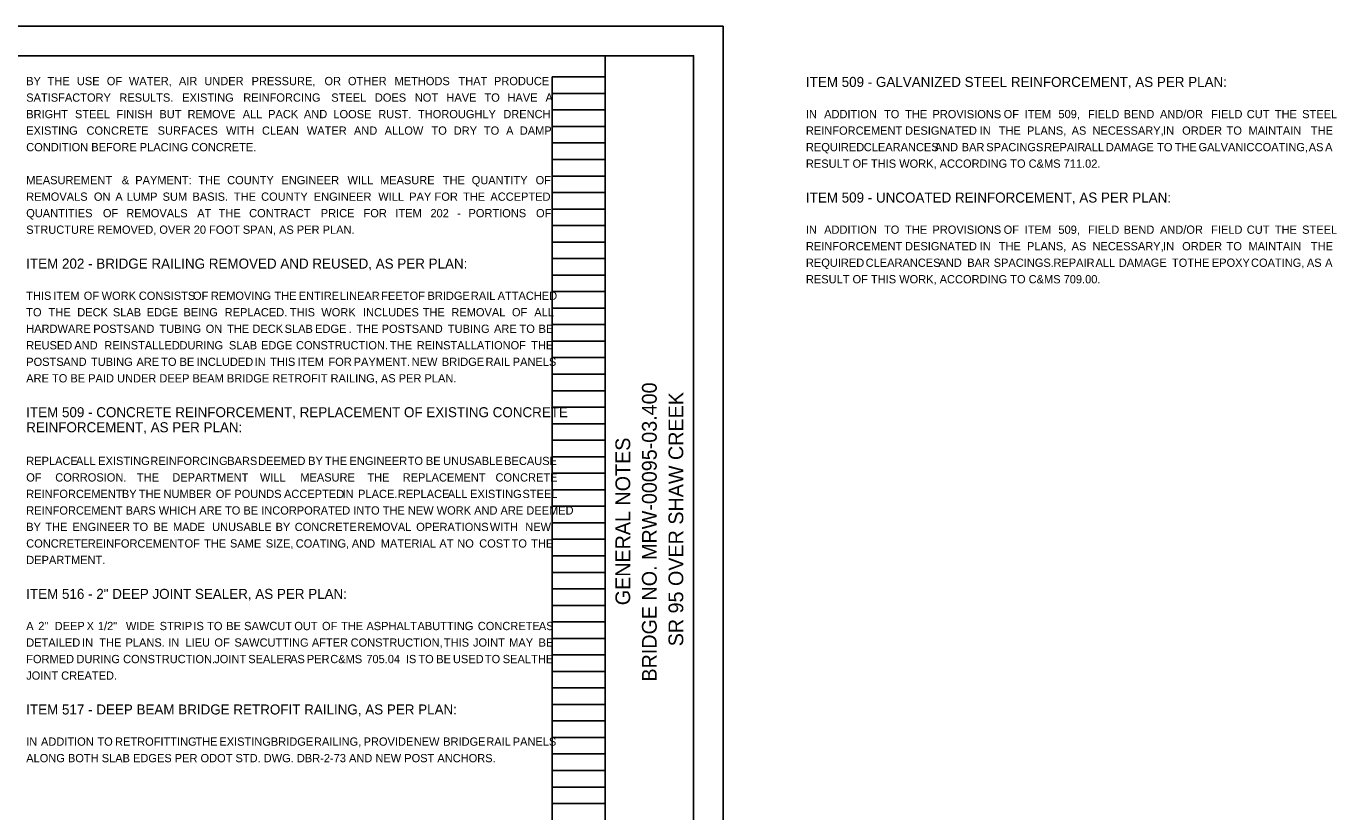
# Model space of a CAD drawing. Extents: x 0 to 44.4, y -4.7 to 22.
# Drawn here: x 22.19 to 44.4, y 8.68 to 22 of the extents above; entities that cross this region are included whole.
import ezdxf

# ---------------------------------------------------------------- set-up
doc = ezdxf.new("R2010")
doc.units = 0
for name, color, linetype in [('SC_Scratch1', 7, 'Continuous'), ('SH_Border', 7, 'Continuous'), ('SH_Cut_Line', 7, 'Continuous'), ('SH_Data', 7, 'Continuous'), ('SH_Text', 7, 'Continuous')]:
    doc.layers.add(name, color=color, linetype=linetype)

msp = doc.modelspace()

# ---------------------------------------------------------------- linework, layer by layer
at = {"layer": 'SC_Scratch1'}
for p, q in [((31.1, 0.98), (31.1, 21.14)), ((31.1, 21.14), (32, 21.14)), ((32, 0.98), (32, 21.14)), ((31.1, 20.86), (32, 20.86)), ((31.1, 20.58), (32, 20.58)), ((31.1, 20.3), (32, 20.3)), ((31.1, 20.02), (32, 20.02)), ((31.1, 19.74), (32, 19.74)), ((31.1, 19.46), (32, 19.46)), ((31.1, 19.18), (32, 19.18)), ((31.1, 18.9), (32, 18.9)), ((31.1, 18.62), (32, 18.62)), ((31.1, 18.34), (32, 18.34)), ((31.1, 18.06), (32, 18.06)), ((31.1, 17.78), (32, 17.78)), ((31.1, 17.5), (32, 17.5)), ((31.1, 17.22), (32, 17.22)), ((31.1, 16.94), (32, 16.94)), ((31.1, 16.66), (32, 16.66)), ((31.1, 16.38), (32, 16.38)), ((31.1, 16.1), (32, 16.1)), ((31.1, 15.82), (32, 15.82)), ((31.1, 15.54), (32, 15.54)), ((31.1, 15.26), (32, 15.26)), ((31.1, 14.98), (32, 14.98)), ((31.1, 14.7), (32, 14.7)), ((31.1, 14.42), (32, 14.42)), ((31.1, 14.14), (32, 14.14)), ((31.1, 13.86), (32, 13.86)), ((31.1, 13.58), (32, 13.58)), ((31.1, 13.3), (32, 13.3)), ((31.1, 13.02), (32, 13.02)), ((31.1, 12.74), (32, 12.74)), ((31.1, 12.46), (32, 12.46)), ((31.1, 12.18), (32, 12.18)), ((31.1, 11.9), (32, 11.9)), ((31.1, 11.62), (32, 11.62)), ((31.1, 11.34), (32, 11.34)), ((31.1, 11.06), (32, 11.06)), ((31.1, 10.78), (32, 10.78)), ((31.1, 10.5), (32, 10.5)), ((31.1, 10.22), (32, 10.22)), ((31.1, 9.94), (32, 9.94)), ((31.1, 9.66), (32, 9.66)), ((31.1, 9.38), (32, 9.38)), ((31.1, 9.1), (32, 9.1)), ((31.1, 8.82), (32, 8.82))]:
    msp.add_line(p, q, dxfattribs=at)
msp.add_lwpolyline([(0, 22), (34, 22), (34, 0), (0, 0)], close=True, dxfattribs=at)
at = {"layer": 'SH_Border'}
msp.add_line((32, 0.5), (32, 21.5), dxfattribs=at)
msp.add_lwpolyline([(1.5, 21.5), (33.5, 21.5), (33.5, 0.5), (1.5, 0.5)], close=True, dxfattribs=at)
at = {"layer": 'SH_Cut_Line'}
msp.add_lwpolyline([(0, 0), (34, 0), (34, 22), (0, 22)], close=True, dxfattribs=at)

# ---------------------------------------------------------------- texts
at = {"layer": 'SH_Data'}
for s, p in [('BRIDGE NO. MRW-00095-03.400', (32.875, 10.888)), ('SR 95 OVER SHAW CREEK', (33.325, 11.486)), ('GENERAL NOTES', (32.425, 12.182))]:
    msp.add_text(s, height=0.25, rotation=90, dxfattribs=at).set_placement(p)
at = {"layer": 'SH_Text'}
for s, height, p in [('BY ', 0.14, (22.187, 21)), ('THE ', 0.14, (22.549, 21)), ('USE ', 0.14, (23.046, 21)), ('OF ', 0.14, (23.553, 21)), ('WATER, ', 0.14, (23.927, 21)), ('AIR ', 0.14, (24.775, 21)), ('UNDER ', 0.14, (25.206, 21)), ('PRESSURE, ', 0.14, (26.007, 21)), ('OR ', 0.14, (27.243, 21)), ('OTHER ', 0.14, (27.641, 21)), ('METHODS ', 0.14, (28.431, 21)), ('THAT ', 0.14, (29.515, 21)), ('PRODUCE ', 0.14, (30.116, 21)), ('ITEM 509 - GALVANIZED STEEL REINFORCEMENT, AS PER PLAN:', 0.17, (35.404, 20.97)), ('SATISFACTORY ', 0.14, (22.187, 20.72)), ('RESULTS. ', 0.14, (23.766, 20.72)), ('EXISTING ', 0.14, (24.831, 20.72)), ('REINFORCING ', 0.14, (25.866, 20.72)), ('STEEL ', 0.14, (27.358, 20.72)), ('DOES ', 0.14, (28.097, 20.72)), ('NOT ', 0.14, (28.774, 20.72)), ('HAVE ', 0.14, (29.31, 20.72)), ('TO ', 0.14, (29.955, 20.72)), ('HAVE ', 0.14, (30.345, 20.72)), ('A', 0.14, (30.99, 20.72)), ('BRIGHT ', 0.14, (22.187, 20.44)), ('STEEL ', 0.14, (23.013, 20.44)), ('FINISH ', 0.14, (23.716, 20.44)), ('BUT ', 0.14, (24.444, 20.44)), ('REMOVE ', 0.14, (24.922, 20.44)), ('ALL ', 0.14, (25.857, 20.44)), ('PACK ', 0.14, (26.288, 20.44)), ('AND ', 0.14, (26.894, 20.44)), ('LOOSE ', 0.14, (27.394, 20.44)), ('RUST. ', 0.14, (28.155, 20.44)), ('THOROUGHLY ', 0.14, (28.828, 20.44)), ('DRENCH ', 0.14, (30.274, 20.44)), ('IN ', 0.14, (35.404, 20.44)), ('ADDITION ', 0.14, (35.713, 20.44)), ('TO ', 0.14, (36.728, 20.44)), ('THE ', 0.14, (37.086, 20.44)), ('PROVISIONS ', 0.14, (37.549, 20.44)), ('OF ', 0.14, (38.756, 20.44)), ('ITEM ', 0.14, (39.113, 20.44)), ('509, ', 0.14, (39.684, 20.44)), ('FIELD ', 0.14, (40.185, 20.44)), ('BEND ', 0.14, (40.79, 20.44)), ('AND/OR ', 0.14, (41.406, 20.44)), ('FIELD ', 0.14, (42.273, 20.44)), ('CUT ', 0.14, (42.877, 20.44)), ('THE ', 0.14, (43.353, 20.44)), ('STEEL ', 0.14, (43.816, 20.44)), ('EXISTING ', 0.14, (22.187, 20.16)), ('CONCRETE ', 0.14, (23.209, 20.16)), ('SURFACES ', 0.14, (24.415, 20.16)), ('WITH ', 0.14, (25.575, 20.16)), ('CLEAN ', 0.14, (26.183, 20.16)), ('WATER ', 0.14, (26.944, 20.16)), ('AND ', 0.14, (27.742, 20.16)), ('ALLOW ', 0.14, (28.263, 20.16)), ('TO ', 0.14, (29.057, 20.16)), ('DRY ', 0.14, (29.434, 20.16)), ('TO ', 0.14, (29.945, 20.16)), ('A ', 0.14, (30.322, 20.16)), ('DAMP ', 0.14, (30.554, 20.16)), ('REINFORCEMENT ', 0.14, (35.404, 20.16)), ('DESIGNATED ', 0.14, (37.085, 20.16)), ('IN ', 0.14, (38.349, 20.16)), ('THE ', 0.14, (38.673, 20.16)), ('PLANS, ', 0.14, (39.151, 20.16)), ('AS ', 0.14, (39.908, 20.16)), ('NECESSARY, ', 0.14, (40.262, 20.16)), ('IN ', 0.14, (41.459, 20.16)), ('ORDER ', 0.14, (41.782, 20.16)), ('TO ', 0.14, (42.535, 20.16)), ('MAINTAIN ', 0.14, (42.907, 20.16)), ('THE ', 0.14, (43.964, 20.16)), ('CONDITION BEFORE PLACING CONCRETE. ', 0.14, (22.187, 19.88)), ('REQUIRED ', 0.14, (35.404, 19.88)), ('CLEARANCES ', 0.14, (36.385, 19.88)), ('AND ', 0.14, (37.588, 19.88)), ('BAR ', 0.14, (38.045, 19.88)), ('SPACINGS. ', 0.14, (38.461, 19.88)), ('REPAIR ', 0.14, (39.443, 19.88)), ('ALL ', 0.14, (40.125, 19.88)), ('DAMAGE ', 0.14, (40.489, 19.88)), ('TO ', 0.14, (41.358, 19.88)), ('THE ', 0.14, (41.656, 19.88)), ('GALVANIC ', 0.14, (42.06, 19.88)), ('COATING, ', 0.14, (43.011, 19.88)), ('AS ', 0.14, (43.927, 19.88)), ('A ', 0.14, (44.206, 19.88)), ('RESULT OF THIS WORK, ACCORDING TO C&MS 711.02.', 0.14, (35.404, 19.6)), ('MEASUREMENT ', 0.14, (22.187, 19.32)), ('& ', 0.14, (23.806, 19.32)), ('PAYMENT: ', 0.14, (24.035, 19.32)), ('THE ', 0.14, (25.104, 19.32)), ('COUNTY ', 0.14, (25.593, 19.32)), ('ENGINEER ', 0.14, (26.513, 19.32)), ('WILL ', 0.14, (27.633, 19.32)), ('MEASURE ', 0.14, (28.184, 19.32)), ('THE ', 0.14, (29.249, 19.32)), ('QUANTITY ', 0.14, (29.739, 19.32)), ('OF ', 0.14, (30.822, 19.32)), ('REMOVALS ', 0.14, (22.187, 19.04)), ('ON ', 0.14, (23.334, 19.04)), ('A ', 0.14, (23.698, 19.04)), ('LUMP ', 0.14, (23.892, 19.04)), ('SUM ', 0.14, (24.499, 19.04)), ('BASIS. ', 0.14, (25.005, 19.04)), ('THE ', 0.14, (25.707, 19.04)), ('COUNTY ', 0.14, (26.169, 19.04)), ('ENGINEER ', 0.14, (27.062, 19.04)), ('WILL ', 0.14, (28.155, 19.04)), ('PAY ', 0.14, (28.679, 19.04)), ('FOR ', 0.14, (29.109, 19.04)), ('THE ', 0.14, (29.592, 19.04)), ('ACCEPTED ', 0.14, (30.055, 19.04)), ('ITEM 509 - UNCOATED REINFORCEMENT, AS PER PLAN:', 0.17, (35.404, 19.01)), ('QUANTITIES ', 0.14, (22.187, 18.76)), ('OF ', 0.14, (23.487, 18.76)), ('REMOVALS ', 0.14, (23.883, 18.76)), ('AT ', 0.14, (25.086, 18.76)), ('THE ', 0.14, (25.448, 18.76)), ('CONTRACT ', 0.14, (25.966, 18.76)), ('PRICE ', 0.14, (27.18, 18.76)), ('FOR ', 0.14, (27.905, 18.76)), ('ITEM ', 0.14, (28.445, 18.76)), ('202 ', 0.14, (29.039, 18.76)), ('PORTIONS ', 0.14, (29.684, 18.76)), ('OF ', 0.14, (30.829, 18.76)), ('- ', 0.14, (29.492, 18.76)), ('STRUCTURE REMOVED, OVER 20 FOOT SPAN, AS PER PLAN.    ', 0.14, (22.187, 18.48)), ('IN ', 0.14, (35.404, 18.48)), ('ADDITION ', 0.14, (35.713, 18.48)), ('TO ', 0.14, (36.728, 18.48)), ('THE ', 0.14, (37.086, 18.48)), ('PROVISIONS ', 0.14, (37.549, 18.48)), ('OF ', 0.14, (38.756, 18.48)), ('ITEM ', 0.14, (39.113, 18.48)), ('509, ', 0.14, (39.684, 18.48)), ('FIELD ', 0.14, (40.185, 18.48)), ('BEND ', 0.14, (40.79, 18.48)), ('AND/OR ', 0.14, (41.406, 18.48)), ('FIELD ', 0.14, (42.273, 18.48)), ('CUT ', 0.14, (42.877, 18.48)), ('THE ', 0.14, (43.353, 18.48)), ('STEEL ', 0.14, (43.816, 18.48)), ('REINFORCEMENT ', 0.14, (35.404, 18.2)), ('DESIGNATED ', 0.14, (37.085, 18.2)), ('IN ', 0.14, (38.349, 18.2)), ('THE ', 0.14, (38.673, 18.2)), ('PLANS, ', 0.14, (39.151, 18.2)), ('AS ', 0.14, (39.908, 18.2)), ('NECESSARY, ', 0.14, (40.262, 18.2)), ('IN ', 0.14, (41.459, 18.2)), ('ORDER ', 0.14, (41.782, 18.2)), ('TO ', 0.14, (42.535, 18.2)), ('MAINTAIN ', 0.14, (42.907, 18.2)), ('THE ', 0.14, (43.964, 18.2)), ('ITEM 202 - BRIDGE RAILING REMOVED AND REUSED, AS PER PLAN:', 0.17, (22.187, 17.89)), ('REQUIRED ', 0.14, (35.404, 17.92)), ('CLEARANCES ', 0.14, (36.417, 17.92)), ('AND ', 0.14, (37.651, 17.92)), ('BAR ', 0.14, (38.139, 17.92)), ('SPACINGS. ', 0.14, (38.587, 17.92)), ('REPAIR ', 0.14, (39.6, 17.92)), ('ALL ', 0.14, (40.313, 17.92)), ('DAMAGE ', 0.14, (40.708, 17.92)), ('TOTHE ', 0.14, (41.609, 17.92)), ('EPOXY ', 0.14, (42.285, 17.92)), ('COATING, ', 0.14, (42.949, 17.92)), ('AS ', 0.14, (43.896, 17.92)), ('A ', 0.14, (44.206, 17.92)), ('RESULT OF THIS WORK, ACCORDING TO C&MS 709.00.  ', 0.14, (35.404, 17.64)), ('THIS ', 0.14, (22.187, 17.36)), ('ITEM ', 0.14, (22.645, 17.36)), ('OF ', 0.14, (23.162, 17.36)), ('WORK ', 0.14, (23.465, 17.36)), ('CONSISTS ', 0.14, (24.096, 17.36)), ('OF ', 0.14, (25.014, 17.36)), ('REMOVING ', 0.14, (25.317, 17.36)), ('THE ', 0.14, (26.395, 17.36)), ('ENTIRE ', 0.14, (26.805, 17.36)), ('LINEAR ', 0.14, (27.503, 17.36)), ('FEET ', 0.14, (28.204, 17.36)), ('OF ', 0.14, (28.686, 17.36)), ('BRIDGE ', 0.14, (28.989, 17.36)), ('RAIL ', 0.14, (29.724, 17.36)), ('ATTACHED ', 0.14, (30.178, 17.36)), ('TO ', 0.14, (22.187, 17.08)), ('THE ', 0.14, (22.566, 17.08)), ('DECK ', 0.14, (23.052, 17.08)), ('SLAB ', 0.14, (23.656, 17.08)), ('EDGE ', 0.14, (24.229, 17.08)), ('BEING ', 0.14, (24.853, 17.08)), ('REPLACED. ', 0.14, (25.551, 17.08)), ('THIS ', 0.14, (26.656, 17.08)), ('WORK ', 0.14, (27.189, 17.08)), ('INCLUDES ', 0.14, (27.896, 17.08)), ('THE ', 0.14, (28.908, 17.08)), ('REMOVAL ', 0.14, (29.394, 17.08)), ('OF ', 0.14, (30.421, 17.08)), ('ALL ', 0.14, (30.8, 17.08)), ('HARDWARE ', 0.14, (22.187, 16.8)), ('POSTS ', 0.14, (23.323, 16.8)), ('AND ', 0.14, (23.964, 16.8)), ('TUBING ', 0.14, (24.446, 16.8)), ('ON ', 0.14, (25.229, 16.8)), ('THE ', 0.14, (25.592, 16.8)), ('DECK ', 0.14, (26.021, 16.8)), ('SLAB ', 0.14, (26.567, 16.8)), ('EDGE ', 0.14, (27.084, 16.8)), ('THE ', 0.14, (27.783, 16.8)), ('POSTS ', 0.14, (28.212, 16.8)), ('AND ', 0.14, (28.852, 16.8)), ('TUBING ', 0.14, (29.335, 16.8)), ('ARE ', 0.14, (30.117, 16.8)), ('TO ', 0.14, (30.549, 16.8)), ('BE ', 0.14, (30.872, 16.8)), ('. ', 0.14, (27.651, 16.8)), ('REUSED ', 0.14, (22.187, 16.52)), ('AND ', 0.14, (23.002, 16.52)), ('REINSTALLED ', 0.14, (23.511, 16.52)), ('DURING ', 0.14, (24.785, 16.52)), ('SLAB ', 0.14, (25.623, 16.52)), ('EDGE ', 0.14, (26.166, 16.52)), ('CONSTRUCTION. ', 0.14, (26.76, 16.52)), ('THE ', 0.14, (28.352, 16.52)), ('REINSTALLATION ', 0.14, (28.807, 16.52)), ('OF ', 0.14, (30.398, 16.52)), ('THE ', 0.14, (30.747, 16.52)), ('POSTS ', 0.14, (22.187, 16.24)), ('AND ', 0.14, (22.815, 16.24)), ('TUBING ', 0.14, (23.285, 16.24)), ('ARE ', 0.14, (24.056, 16.24)), ('TO ', 0.14, (24.475, 16.24)), ('BE ', 0.14, (24.786, 16.24)), ('INCLUDED ', 0.14, (25.078, 16.24)), ('IN ', 0.14, (26.059, 16.24)), ('THIS ', 0.14, (26.322, 16.24)), ('ITEM ', 0.14, (26.787, 16.24)), ('FOR ', 0.14, (27.31, 16.24)), ('PAYMENT. ', 0.14, (27.738, 16.24)), ('NEW ', 0.14, (28.721, 16.24)), ('BRIDGE ', 0.14, (29.232, 16.24)), ('RAIL ', 0.14, (29.974, 16.24)), ('PANELS ', 0.14, (30.434, 16.24)), ('ARE TO BE PAID UNDER DEEP BEAM BRIDGE RETROFIT RAILING, AS PER PLAN.', 0.14, (22.187, 15.96)), ('ITEM 509 - CONCRETE REINFORCEMENT, REPLACEMENT OF EXISTING CONCRETE ', 0.17, (22.187, 15.37)), ('REINFORCEMENT, AS PER PLAN:', 0.17, (22.187, 15.115)), ('REPLACE ', 0.14, (22.187, 14.56)), ('ALL ', 0.14, (23.03, 14.56)), ('EXISTING ', 0.14, (23.407, 14.56)), ('REINFORCING ', 0.14, (24.291, 14.56)), ('BARS ', 0.14, (25.594, 14.56)), ('DEEMED ', 0.14, (26.119, 14.56)), ('BY ', 0.14, (26.966, 14.56)), ('THE ', 0.14, (27.251, 14.56)), ('ENGINEER ', 0.14, (27.667, 14.56)), ('TO ', 0.14, (28.653, 14.56)), ('BE ', 0.14, (28.962, 14.56)), ('UNUSABLE ', 0.14, (29.254, 14.56)), ('BECAUSE ', 0.14, (30.289, 14.56)), ('OF ', 0.14, (22.187, 14.28)), ('CORROSION. ', 0.14, (22.679, 14.28)), ('THE ', 0.14, (24.063, 14.28)), ('DEPARTMENT ', 0.14, (24.663, 14.28)), ('WILL ', 0.14, (26.148, 14.28)), ('MEASURE ', 0.14, (26.833, 14.28)), ('THE ', 0.14, (27.97, 14.28)), ('REPLACEMENT ', 0.14, (28.569, 14.28)), ('CONCRETE ', 0.14, (30.142, 14.28)), ('REINFORCEMENT ', 0.14, (22.187, 14)), ('BY ', 0.14, (23.809, 14)), ('THE ', 0.14, (24.096, 14)), ('NUMBER ', 0.14, (24.515, 14)), ('OF ', 0.14, (25.401, 14)), ('POUNDS ', 0.14, (25.714, 14)), ('ACCEPTED ', 0.14, (26.557, 14)), ('IN ', 0.14, (27.549, 14)), ('PLACE. ', 0.14, (27.813, 14)), ('REPLACE ', 0.14, (28.487, 14)), ('ALL ', 0.14, (29.333, 14)), ('EXISTING ', 0.14, (29.712, 14)), ('STEEL ', 0.14, (30.599, 14)), ('REINFORCEMENT BARS WHICH ARE TO BE INCORPORATED INTO THE NEW WORK AND ARE DEEMED ', 0.14, (22.187, 13.72)), ('BY ', 0.14, (22.187, 13.44)), ('THE ', 0.14, (22.511, 13.44)), ('ENGINEER ', 0.14, (22.968, 13.44)), ('TO ', 0.14, (23.994, 13.44)), ('BE ', 0.14, (24.343, 13.44)), ('MADE ', 0.14, (24.675, 13.44)), ('UNUSABLE ', 0.14, (25.338, 13.44)), ('BY ', 0.14, (26.414, 13.44)), ('CONCRETE ', 0.14, (26.739, 13.44)), ('REMOVAL ', 0.14, (27.8, 13.44)), ('OPERATIONS ', 0.14, (28.798, 13.44)), ('WITH ', 0.14, (30.046, 13.44)), ('NEW ', 0.14, (30.647, 13.44)), ('CONCRETE ', 0.14, (22.187, 13.16)), ('REINFORCEMENT ', 0.14, (23.23, 13.16)), ('OF ', 0.14, (24.871, 13.16)), ('THE ', 0.14, (25.202, 13.16)), ('SAME ', 0.14, (25.641, 13.16)), ('SIZE, ', 0.14, (26.249, 13.16)), ('COATING, ', 0.14, (26.756, 13.16)), ('AND ', 0.14, (27.706, 13.16)), ('MATERIAL ', 0.14, (28.197, 13.16)), ('AT ', 0.14, (29.191, 13.16)), ('NO ', 0.14, (29.494, 13.16)), ('COST ', 0.14, (29.866, 13.16)), ('TO ', 0.14, (30.415, 13.16)), ('THE ', 0.14, (30.747, 13.16)), ('DEPARTMENT.', 0.14, (22.187, 12.88)), ('ITEM 516 - 2" DEEP JOINT SEALER, AS PER PLAN:', 0.17, (22.187, 12.29)), ('A ', 0.14, (22.187, 11.76)), ('2" ', 0.14, (22.391, 11.76)), ('DEEP ', 0.14, (22.669, 11.76)), ('X ', 0.14, (23.211, 11.76)), ('1/2" ', 0.14, (23.402, 11.76)), ('WIDE ', 0.14, (23.877, 11.76)), ('STRIP ', 0.14, (24.449, 11.76)), ('IS ', 0.14, (25.021, 11.76)), ('TO ', 0.14, (25.254, 11.76)), ('BE ', 0.14, (25.577, 11.76)), ('SAWCUT ', 0.14, (25.882, 11.76)), ('OUT ', 0.14, (26.731, 11.76)), ('OF ', 0.14, (27.201, 11.76)), ('THE ', 0.14, (27.524, 11.76)), ('ASPHALT ', 0.14, (27.954, 11.76)), ('ABUTTING ', 0.14, (28.82, 11.76)), ('CONCRETE ', 0.14, (29.842, 11.76)), ('AS ', 0.14, (30.877, 11.76)), ('DETAILED ', 0.14, (22.187, 11.48)), ('IN ', 0.14, (23.134, 11.48)), ('THE ', 0.14, (23.425, 11.48)), ('PLANS. ', 0.14, (23.87, 11.48)), ('IN ', 0.14, (24.595, 11.48)), ('LIEU ', 0.14, (24.886, 11.48)), ('OF ', 0.14, (25.377, 11.48)), ('SAWCUTTING ', 0.14, (25.716, 11.48)), ('AFTER ', 0.14, (27.029, 11.48)), ('CONSTRUCTION, ', 0.14, (27.686, 11.48)), ('THIS ', 0.14, (29.267, 11.48)), ('JOINT ', 0.14, (29.76, 11.48)), ('MAY ', 0.14, (30.374, 11.48)), ('BE ', 0.14, (30.872, 11.48)), ('FORMED ', 0.14, (22.187, 11.2)), ('DURING ', 0.14, (23.038, 11.2)), ('CONSTRUCTION. ', 0.14, (23.829, 11.2)), ('JOINT ', 0.14, (25.374, 11.2)), ('SEALER ', 0.14, (25.951, 11.2)), ('AS ', 0.14, (26.66, 11.2)), ('PER ', 0.14, (26.944, 11.2)), ('C&MS ', 0.14, (27.341, 11.2)), ('705.04 ', 0.14, (27.952, 11.2)), ('IS ', 0.14, (28.623, 11.2)), ('TO ', 0.14, (28.835, 11.2)), ('BE ', 0.14, (29.137, 11.2)), ('USED ', 0.14, (29.421, 11.2)), ('TO ', 0.14, (29.962, 11.2)), ('SEAL ', 0.14, (30.265, 11.2)), ('THE ', 0.14, (30.747, 11.2)), ('JOINT CREATED.', 0.14, (22.187, 10.92)), ('ITEM 517 - DEEP BEAM BRIDGE RETROFIT RAILING, AS PER PLAN:', 0.17, (22.187, 10.33)), ('IN ', 0.14, (22.187, 9.8)), ('ADDITION ', 0.14, (22.437, 9.8)), ('TO ', 0.14, (23.394, 9.8)), ('RETROFITTING ', 0.14, (23.693, 9.8)), ('THE ', 0.14, (25.055, 9.8)), ('EXISTING ', 0.14, (25.461, 9.8)), ('BRIDGE ', 0.14, (26.334, 9.8)), ('RAILING, ', 0.14, (27.065, 9.8)), ('PROVIDE ', 0.14, (27.906, 9.8)), ('NEW ', 0.14, (28.756, 9.8)), ('BRIDGE ', 0.14, (29.255, 9.8)), ('RAIL ', 0.14, (29.986, 9.8)), ('PANELS ', 0.14, (30.434, 9.8)), ('ALONG BOTH SLAB EDGES PER ODOT STD. DWG. DBR-2-73 AND NEW POST ANCHORS.', 0.14, (22.187, 9.52))]:
    msp.add_text(s, height=height, dxfattribs=at).set_placement(p)

doc.saveas('drawing.dxf')
